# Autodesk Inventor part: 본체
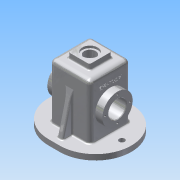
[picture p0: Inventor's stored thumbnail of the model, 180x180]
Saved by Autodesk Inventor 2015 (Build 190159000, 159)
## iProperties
Created: 2017-07
Part Number: 본체
Material: 알루미늄 6061
Document SubType Name: Modeling
Designer: Administrator
Density: 2.7 g/cm^3
Appearance: 알루미늄 - 평지
Mass: 1003.2 g
Surface Area: 1095.96 cm^2
Volume: 371.556 cm^3
Author: Administrator
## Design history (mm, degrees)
sketch "스케치2"
  geometry: L1 (37, -37)-(-37, -37); L2 (-37, -37)-(-37, 37); L3 (-37, 37)-(37, 37); L4 (37, 37)-(37, -37); L5 (37, -37)-(-37, 37); L6 (-37, -37)-(37, 37); 1 further point
  constraints: 12 end point, 2 midpoint, 2 parallel, 1 horizontal, 1 perpendicular
  dimensions: "d2" = 74 distance between parallel lines of L2 L4; "d3" = 74 distance between parallel lines of L3 L1
extrude "돌출1" new body sketch "스케치2" distance "d4" = 110; taper "d5" = 0 deg
fillet "모깎기1" dims "d6" = 8
sketch "스케치3"
  geometry: L1 (74, 0)-(0, 0) reference; L2 (74, 0)-(74, 102) reference; C1 r 27.5 at (37, 55); 1 further point
  constraints: 1 centre point
  dimensions: "d7" = 55 distance from line of L1 C1.centre; "d8" = 37 distance from line of L2 C1.centre; "d11" = 55 diameter of C1
extrude "돌출2" join sketch "스케치3" distance "d12" = 13; taper "d13" = 0 deg
sketch "스케치4"
  geometry: L1 (74, 0)-(0, 0) reference; C1 r 27.5 at (37, 55); 2 further points
  constraints: 1 centre point, 1 midpoint, 1 vertical alignment
  dimensions: "d14" = 55 diameter of C1; "d15" = 55 distance from line of L1 C1.centre
extrude "돌출3" join sketch "스케치4" distance "d16" = 13; taper "d17" = 0 deg
sketch "스케치5"
  geometry: L1 (29, 110)-(-29, 110) reference; L2 (37, 0)-(37, 102) reference; L3 (-37, 0)-(37, 0) reference; L4 (-37, 0)-(-37, 102) reference; L5 (29, 105)-(-29, 105); L6 (-32, 102)-(-32, 0); L7 (32, 0)-(32, 102); L8 (-32, 0)-(32, 0); A1 r 8 centre (-29, 102) between (-29, 110) and (-37, 102) reference; A2 r 8 centre (29, 102) between (37, 102) and (29, 110) reference; A3 r 3 centre (29, 102) between (32, 102) and (29, 105); A4 r 3 centre (-29, 102) between (-29, 105) and (-32, 102); 1 further point
  constraints: 8 end point, 4 point on circle, 2 centre point, 2 point on line, 1 collinear, 1 tangent, 2 other
  dimensions: "d18" = 5 distance between parallel lines of L2 L7; "d19" = 64 distance between parallel lines of L7 L6
extrude "돌출4" cut sketch "스케치5" stored distance "d20" = 64; taper "d21" = 0 deg
sketch "스케치6"
  geometry: L1 (32, 0)-(-32, 0) reference; L2 (-25, 55)-(-32, 55); L3 (-32, 0)-(-32, 102) reference; L4 (-25, 75.5)-(-25, 55); L5 (-25, 75.5)-(-32, 82.5); L6 (-32, 82.5)-(-32, 55); 1 further point
  constraints: 8 end point, 1 collinear, 1 parallel, 1 point on line
  dimensions: "d22" = 55 distance between parallel lines of L1 L2; "d24" = 7 distance between parallel lines of L3 L4; "d26" = 135 deg angle of L4 L5; "d90" = 27.5 distance of L2.end L5.end
revolve "회전1" sketch "스케치6" stored, may be unused: angle "d28" = 90 deg
sketch "스케치7"
  geometry: C1 r 16 at (0, 0); 2 further points
  constraints: 1 centre point, 1 coincident
  dimensions: "d30" = 32 diameter of C1
extrude "돌출5" cut sketch "스케치7" stored distance "d31" = 40; taper "d32" = 0 deg
sketch "스케치8"
  geometry: C1 r 16 at (0, 0) reference; 2 further points
  constraints: 1 vertical alignment
  dimensions: "d33" = 22.5 distance of C1.centre point (0, 22.5)
hole "구멍1" sketch "스케치8" at (0, 22.5) diameter "d34" = 3.242; stored, may be unused: countersink angle "d38" = 90 deg, drill point angle "d40" = 118 deg; dims "d35" = 8, "d36" = 4, "d37" = 2, "d39" = 10
sketch "스케치9"
  geometry: L1 (-20, 20)-(20, 20); L2 (20, 20)-(20, -20); L3 (20, -20)-(-20, -20); L4 (-20, -20)-(-20, 20); L5 (-20, 20)-(20, -20); L6 (20, 20)-(-20, -20); 1 further point
  constraints: 12 end point, 2 midpoint, 2 parallel, 1 horizontal, 1 perpendicular
  dimensions: "d44" = 40 distance between parallel lines of L2 L4; "d45" = 40 distance between parallel lines of L3 L1
extrude "돌출6" join sketch "스케치9" distance "d46" = 10; taper "d47" = 0 deg
feature "면 기울기1" dims angle "d48" = 5 deg
feature "면 기울기2" dims angle "d49" = 5 deg
sketch "스케치10"
  geometry: C1 r 14 at (0, 0); 1 further point
  constraints: 1 centre point, 1 coincident
  dimensions: "d52" = 28 diameter of C1
extrude "돌출7" cut sketch "스케치10" distance "d53" = 4; taper "d54" = 0 deg
sketch "스케치11"
  geometry: C1 r 14 at (0, 0) reference; C2 r 10.5 at (0, 0)
  constraints: 1 centre point, 1 coincident
  dimensions: "d55" = 21 diameter of C2
extrude "돌출8" cut sketch "스케치11" distance "d56" = 50; taper "d57" = 0 deg
sketch "스케치12"
  geometry: L1 (-29, -37)-(29, -37) reference; L2 (29, 37)-(-29, 37) reference; L3 (-37, 37)-(-37, -37) reference; L4 (37, -37)-(37, 37) reference; L5 (75, -65)-(-75, -65); L6 (-75, -65)-(-75, 65); L7 (-75, 65)-(75, 65); L8 (75, 65)-(75, -65); L9 (75, -65)-(-75, 65); L10 (-75, -65)-(75, 65); 1 further point
  constraints: 12 end point, 2 midpoint, 2 parallel, 1 horizontal, 1 perpendicular
  dimensions: "d58" = 150 distance between parallel lines of L8 L6; "d59" = 130 distance between parallel lines of L7 L5
extrude "돌출9" join sketch "스케치12" distance "d60" = 10; taper "d61" = 0 deg
sketch "스케치13"
  geometry: L1 (-32, 32)-(32, 32); L2 (32, 32)-(32, -32); L3 (32, -32)-(-32, -32); L4 (-32, -32)-(-32, 32); L5 (-32, 32)-(32, -32); L6 (32, 32)-(-32, -32); 1 further point
  constraints: 12 end point, 2 midpoint, 2 parallel, 1 horizontal, 1 perpendicular
  dimensions: "d62" = 64 distance between parallel lines of L4 L2; "d63" = 64 distance between parallel lines of L3 L1
extrude "돌출10" cut sketch "스케치13" distance "d64" = 10; taper "d65" = 0 deg
sketch "스케치14"
  geometry: C1 r 5 at (58, 0); 1 further point
  constraints: 1 centre point, 1 horizontal alignment
  dimensions: "d67" = 10 diameter of C1; "d68" = 58 distance of point (0, 0) C1.centre
extrude "돌출11" cut sketch "스케치14" distance "d69" = 10; taper "d70" = 0 deg
fillet "모깎기2" dims "d74" = 3
fillet "모깎기3" dims "d75" = 3
fillet "모깎기4" dims "d76" = 8
sketch "스케치15"
  geometry: L1 (10, 55)-(82.194, 37); L2 (10, -65)-(10, 65) reference; L3 (10, 37)-(102, 37) reference; L4 (82.194, 37)-(10, 37); L5 (10, 55)-(10, 37); 2 further points
  constraints: 6 end point, 3 point on line, 1 collinear
  dimensions: "d80" = 104 deg angle of L2 L1; "d81" = 90 deg angle of L4 L2; "d82" = 4.79149 distance from line of L3.end L1
extrude "돌출12" join sketch "스케치15" stored distance "d83" = 10; taper "d84" = 0 deg
fillet "모깎기6" dims "d85" = 3
fillet "모깎기7" dims "d86" = 3
chamfer "모따기1" distance "d87" = 1; stored, may be unused: second distance "d88" = 2, angle "d89" = 45 deg
sketch "스케치16"
  geometry: L1 (12, 18)-(46, 18) reference; L2 (66, -89)-(66, 0) reference; 2 further points
  constraints: 1 other
  dimensions: "d91" = 30 distance from line of point (29, -12) L1; "d92" = 37 distance from line of L2 point (29, -12)
feature "엠보싱1" sketch "스케치16" dims "d93" = 0.5, "d94" = 0
fillet "모깎기8" dims "d95" = 3
fillet "모깎기9" dims "d96" = 65
fillet "모깎기10" dims "d97" = 65
fillet "모깎기11" dims "d98" = 65
fillet "모깎기12" dims "d99" = 65
node "솔리드1"
mirror "대칭1"
pattern_circular "원형 패턴1" dims angle "d42" = 360 deg
mirror "대칭2"
pattern_linear "직사각형 패턴1" dims "d73" = 116
mirror "대칭3"
node "투영된 루프1"
